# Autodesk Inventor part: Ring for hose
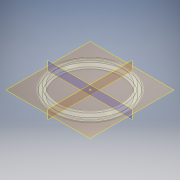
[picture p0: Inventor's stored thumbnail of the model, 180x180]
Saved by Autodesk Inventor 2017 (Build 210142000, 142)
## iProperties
Created: 2020-03
Part Number: Ring for hose
Material: Polycarbonate, Clear
Document SubType Name: Modeling
Designer: user
Density: 1.2 g/cm^3
Appearance: Polycarbonate - Clear
Author: user
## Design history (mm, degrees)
sketch "Sketch1"
  geometry: L1 (12.7, 1.584)-(13.867, 0.845); L2 (13.867, -0.845)-(12.711, -1.577); L3 (0, 0)-(1.052, 0); L4 (12.7, 1.584)-(11.7, 1.584); L5 (12.711, -1.577)-(11.711, -1.577); L6 (11.711, -1.327)-(12.639, -1.327); L7 (12.639, -1.327)-(13.733, -0.634); L8 (13.733, 0.634)-(12.627, 1.334); L9 (12.627, 1.334)-(11.7, 1.334); L10 (11.7, 1.584)-(11.7, 1.334); L11 (11.711, -1.327)-(11.711, -1.577); L12 (0, -2.209)-(0, 2.216) reference; A1 r 1 centre (13.332, 0) between (13.867, -0.845) and (13.867, 0.845); A2 r 0.75 centre (13.332, 0) between (13.733, -0.634) and (13.733, 0.634); 1 further point
  constraints: 22 end point, 4 point on circle, 3 horizontal, 2 centre point, 2 point on line, 2 tangent, 1 parallel, 1 vertical, 5 other
  dimensions: "d1" = 3.16094 distance of L2.end L1.start; "d2" = 12.7 horizontal distance of L3.start L1.start; "d3" = 2.5 horizontal distance of L1.start point (15.2, 0); "d4" = 1 radius of A1; "d5" = 1 distance of L1.start L4.end; "d6" = 1 distance of L2.end L5.end; "d8" = 0.25 distance between parallel lines of L1 L8
revolve "Revolution1" sketch "Sketch1" stored, may be unused: angle "d9" = 90 deg
body "Solid1"
